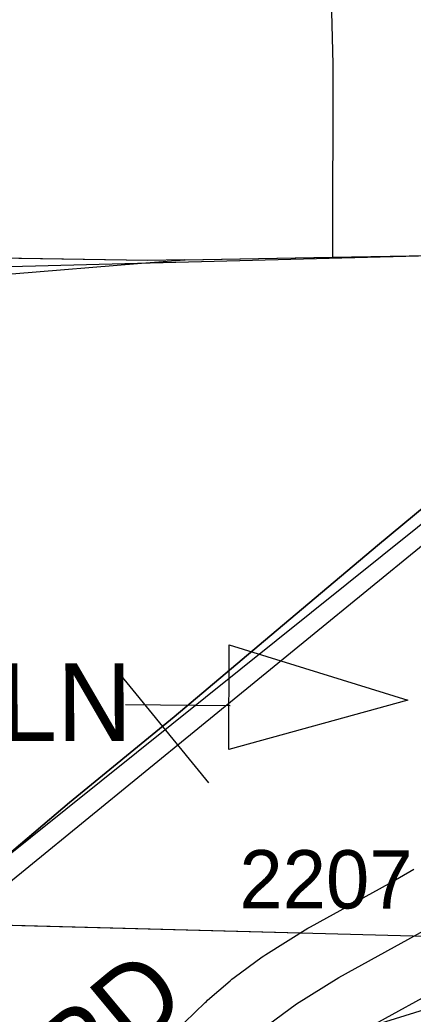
# Model space of a CAD drawing. Extents: x -132.8 to -73.3, y -60 to -26.
# Drawn here: x -118.614 to -118.411, y -48.456 to -47.944 of the extents above; entities that cross this region are included whole.
import ezdxf

# ---------------------------------------------------------------- set-up
doc = ezdxf.new("R2010")
doc.units = 0
for name, color, linetype in [('tdCoCityStreetMajor', 7, 'Continuous'), ('tdCoCorpBndry', 7, 'Continuous'), ('tdCoDirctArrow', 7, 'Continuous'), ('tdCoDivCarto', 7, 'Continuous'), ('tdCoHydroRiver', 7, 'Continuous'), ('tdCoPrimary', 7, 'Continuous'), ('tdCoPriNonDiv', 7, 'Continuous'), ('tdCoPriNonDivCL', 7, 'Continuous'), ('tdCoRRCL', 7, 'Continuous'), ('tdCoSecRdNmbr', 7, 'Continuous'), ('tdCoSecRdTxt', 7, 'Continuous'), ('tdCoSecRteBand', 7, 'Continuous'), ('tdCoSecRteCL', 7, 'Continuous'), ('tdCoSectLine', 7, 'Continuous'), ('tdCoSectLinePart', 7, 'Continuous'), ('tdCoSurfBitum', 7, 'Continuous')]:
    doc.layers.add(name, color=color, linetype=linetype)

msp = doc.modelspace()

# ---------------------------------------------------------------- linework, layer by layer
at = {"layer": 'tdCoCityStreetMajor'}
msp.add_lwpolyline([(-118.45246, -48.06627), (-118.45228, -47.96682), (-118.45549, -47.83809), (-118.45647, -47.76756), (-118.4545, -47.74882), (-118.44858, -47.72909), (-118.43798, -47.70986), (-118.42614, -47.69531), (-118.40765, -47.6815), (-118.38668, -47.67262), (-118.37337, -47.66892), (-118.36119, -47.66821), (-118.36101, -47.6682)], dxfattribs=at)
at = {"layer": 'tdCoCorpBndry'}
msp.add_lwpolyline([(-118.35624, -47.4141), (-118.36119, -47.66821), (-118.3699, -47.97336), (-118.37354, -48.06481), (-118.37608, -48.16042), (-118.37689, -48.19087), (-118.69634, -48.4516), (-118.88124, -48.6063), (-119.00578, -48.72624), (-119.22081, -48.96551)], dxfattribs=at)
at = {"layer": 'tdCoDirctArrow'}
msp.add_line((-118.55933, -48.29678), (-118.50529, -48.2973), dxfattribs=at)
msp.add_lwpolyline([(-118.50583, -48.26602), (-118.41374, -48.29447), (-118.50599, -48.31992)], close=True, dxfattribs=at)
at = {"layer": 'tdCoDivCarto'}
for p, q in [((-118.54791, -48.06798), (-118.63477, -48.06655)), ((-118.55107, -48.06942), (-118.52899, -48.06764)), ((-118.55107, -48.06942), (-118.52899, -48.06764)), ((-118.52899, -48.06764), (-118.54791, -48.06798)), ((-118.61785, -48.07479), (-118.55107, -48.06942)), ((-118.61785, -48.07479), (-118.55107, -48.06942))]:
    msp.add_line(p, q, dxfattribs=at)
for points in [[(-118.52899, -48.06764), (-118.54791, -48.06798), (-118.63477, -48.06655), (-118.67599, -48.06688)], [(-118.52899, -48.06764), (-118.54791, -48.06798), (-118.63477, -48.06655), (-118.67598, -48.06688)], [(-118.52899, -48.06764), (-118.54791, -48.06798), (-118.63477, -48.06655), (-118.67598, -48.06688)], [(-118.55107, -48.06942), (-118.52899, -48.06764)], [(-118.55107, -48.06942), (-118.52899, -48.06764)], [(-118.61785, -48.07479), (-118.55107, -48.06942)], [(-118.61785, -48.07479), (-118.55107, -48.06942)]]:
    msp.add_lwpolyline(points, dxfattribs=at)
at = {"layer": 'tdCoHydroRiver'}
msp.add_lwpolyline([(-117.98585, -48.0942), (-118.01487, -48.11708), (-118.04527, -48.13204), (-118.06628, -48.1504), (-118.0979, -48.21108), (-118.12057, -48.23255), (-118.16562, -48.26447), (-118.21814, -48.2804), (-118.31229, -48.37725), (-118.36757, -48.43729), (-118.38999, -48.4493), (-118.4457, -48.46673), (-118.47166, -48.49285), (-118.50738, -48.52975), (-118.53695, -48.57313), (-118.57957, -48.63193), (-118.60208, -48.64709), (-118.63379, -48.65254), (-118.65762, -48.65821), (-118.69777, -48.68395), (-118.7577, -48.7407), (-118.84316, -48.80781), (-118.87734, -48.84633), (-118.90841, -48.88651)], dxfattribs=at)
at = {"layer": 'tdCoPrimary'}
for p, q in [((-118.55107, -48.06942), (-118.52899, -48.06764)), ((-118.55107, -48.06942), (-118.52899, -48.06764)), ((-118.52899, -48.06764), (-118.52859, -48.06763)), ((-118.52899, -48.06764), (-118.52859, -48.06763)), ((-118.52859, -48.06763), (-118.52857, -48.06763)), ((-118.52859, -48.06763), (-118.52857, -48.06763)), ((-118.61785, -48.07479), (-118.55107, -48.06942)), ((-118.61785, -48.07479), (-118.55107, -48.06942))]:
    msp.add_line(p, q, dxfattribs=at)
for points in [[(-118.52899, -48.06764), (-118.54791, -48.06798), (-118.63477, -48.06655), (-118.67598, -48.06688), (-118.72651, -48.06729), (-118.78287, -48.0686), (-118.78288, -48.0686), (-118.79081, -48.06879), (-118.80074, -48.06902), (-118.82106, -48.07001), (-118.85105, -48.07148), (-118.86386, -48.07176)], [(-118.79917, -48.08377), (-118.74199, -48.08204), (-118.67565, -48.0783), (-118.6283, -48.07563), (-118.61785, -48.07479), (-118.55107, -48.06942), (-118.52899, -48.06764)], [(-118.52899, -48.06764), (-118.54791, -48.06798), (-118.63477, -48.06655), (-118.67598, -48.06688)], [(-118.52899, -48.06764), (-118.54791, -48.06798), (-118.63477, -48.06655), (-118.67598, -48.06688)], [(-118.52899, -48.06764), (-118.52859, -48.06763), (-118.52857, -48.06763), (-118.45246, -48.06627), (-118.45197, -48.06626), (-118.38293, -48.06502)], [(-118.52857, -48.06763), (-118.45246, -48.06627), (-118.45197, -48.06626)], [(-118.52857, -48.06763), (-118.45246, -48.06627), (-118.45197, -48.06626)], [(-118.45197, -48.06626), (-118.38293, -48.06502), (-118.37354, -48.06476)], [(-118.45197, -48.06626), (-118.38293, -48.06502), (-118.37354, -48.06476)]]:
    msp.add_lwpolyline(points, dxfattribs=at)
at = {"layer": 'tdCoPriNonDiv'}
msp.add_lwpolyline([(-118.61889, -48.0711), (-118.3293, -48.06354), (-117.75619, -48.05368), (-117.65212, -48.05121), (-117.45927, -48.03864), (-117.03141, -48.00732), (-116.85509, -47.99375), (-116.65238, -47.97994), (-116.54954, -47.97797), (-115.84942, -47.98956), (-115.38137, -47.99449), (-115.06398, -47.99893)], dxfattribs=at)
at = {"layer": 'tdCoPriNonDivCL'}
for points in [[(-118.52937, -48.06764), (-118.52897, -48.06763), (-118.45284, -48.06627), (-118.38331, -48.06502), (-118.37392, -48.06476), (-118.37392, -48.06476), (-118.37353, -48.06475), (-118.3293, -48.06354), (-118.29791, -48.06338), (-118.2314, -48.06305), (-118.21913, -48.06281), (-118.1298, -48.06108), (-118.09528, -48.06035), (-118.0245, -48.05886), (-117.92277, -48.05679), (-117.89083, -48.05614), (-117.89044, -48.05614), (-117.86458, -48.05566), (-117.86419, -48.05566), (-117.75619, -48.05368), (-117.65212, -48.05121), (-117.56975, -48.04677), (-117.45927, -48.03864), (-117.42909, -48.03615)], [(-118.52897, -48.06763), (-118.45284, -48.06627), (-118.38331, -48.06502), (-118.37392, -48.06476), (-118.37353, -48.06475), (-118.37353, -48.06475), (-118.3293, -48.06354), (-118.29791, -48.06338), (-118.2314, -48.06305), (-118.21913, -48.06281), (-118.1298, -48.06108), (-118.09528, -48.06035), (-118.0245, -48.05886), (-117.92277, -48.05679), (-117.89083, -48.05614), (-117.89044, -48.05614), (-117.86458, -48.05566), (-117.86419, -48.05566), (-117.75619, -48.05368), (-117.65212, -48.05121), (-117.56975, -48.04677), (-117.45927, -48.03864), (-117.42909, -48.03615)]]:
    msp.add_lwpolyline(points, dxfattribs=at)
at = {"layer": 'tdCoRRCL'}
msp.add_line((-118.56397, -48.27909), (-118.51652, -48.33717), dxfattribs=at)
for points in [[(-119.04345, -48.75425), (-119.0096, -48.71656), (-118.97392, -48.67777), (-118.94977, -48.65307), (-118.93586, -48.64062), (-118.91079, -48.61702), (-118.88261, -48.59396), (-118.87411, -48.58703), (-118.85279, -48.56963), (-118.82132, -48.5431), (-118.78637, -48.51345), (-118.75343, -48.48619), (-118.71683, -48.45527), (-118.68902, -48.43185), (-118.64913, -48.39909), (-118.5882, -48.34731), (-118.53422, -48.30321), (-118.49049, -48.26625), (-118.42937, -48.21483), (-118.38418, -48.17732)], [(-118.38418, -48.17732), (-118.42937, -48.21483), (-118.49049, -48.26625), (-118.53422, -48.30321), (-118.5882, -48.34731), (-118.64913, -48.39909), (-118.68902, -48.43185), (-118.71683, -48.45527), (-118.75343, -48.48619), (-118.78637, -48.51345), (-118.82132, -48.5431), (-118.85279, -48.56963), (-118.87411, -48.58703), (-118.88261, -48.59396), (-118.91079, -48.61702), (-118.93586, -48.64062), (-118.94977, -48.65307), (-118.97392, -48.67777), (-119.0096, -48.71656), (-119.04345, -48.75425)], [(-120.90014, -50.91758), (-120.80482, -50.8333), (-120.69913, -50.71459), (-120.38749, -50.3671), (-120.27515, -50.19914), (-119.95857, -49.75638), (-119.76019, -49.4486), (-119.624, -49.31017), (-119.6013, -49.2871), (-119.53026, -49.22585), (-119.46076, -49.16298), (-119.40286, -49.1219), (-119.33353, -49.06534), (-119.1714, -48.90077), (-118.98751, -48.68786), (-118.88892, -48.59894), (-118.66302, -48.40922), (-118.39059, -48.19074)]]:
    msp.add_lwpolyline(points, dxfattribs=at)
at = {"layer": 'tdCoSecRteBand'}
for points in [[(-118.52885, -48.46074), (-118.51825, -48.45039), (-118.51764, -48.4498), (-118.51701, -48.44924), (-118.50542, -48.43913), (-118.50443, -48.43827), (-118.50336, -48.43749), (-118.48881, -48.42689), (-118.48795, -48.42626), (-118.48704, -48.42569), (-118.46534, -48.41213), (-118.46465, -48.4117), (-118.46393, -48.4113), (-118.42344, -48.38897), (-118.41071, -48.38169)], [(-118.39427, -48.4414), (-118.43424, -48.46344)]]:
    msp.add_lwpolyline(points, dxfattribs=at)
at = {"layer": 'tdCoSecRteCL'}
msp.add_lwpolyline([(-118.95499, -48.91056), (-118.90887, -48.8499), (-118.87089, -48.80255), (-118.8598, -48.788), (-118.84993, -48.7769), (-118.83859, -48.7658), (-118.81861, -48.75002), (-118.77891, -48.72166), (-118.65807, -48.63584), (-118.60678, -48.60008), (-118.59346, -48.59047), (-118.58113, -48.57937), (-118.56905, -48.56605), (-118.55573, -48.54756), (-118.53107, -48.51427), (-118.51948, -48.49725), (-118.50789, -48.48221), (-118.49729, -48.47185), (-118.48569, -48.46174), (-118.47114, -48.45113), (-118.44944, -48.43757), (-118.40875, -48.41513), (-118.38976, -48.40428), (-118.38121, -48.39765)], dxfattribs=at)
at = {"layer": 'tdCoSectLine'}
msp.add_lwpolyline([(-118.88204, -48.40349), (-117.88235, -48.43017)], dxfattribs=at)
at = {"layer": 'tdCoSectLinePart'}
msp.add_lwpolyline([(-118.64551, -48.4098), (-118.46943, -48.4145)], dxfattribs=at)
at = {"layer": 'tdCoSurfBitum'}
msp.add_lwpolyline([(-118.95499, -48.91056), (-118.90887, -48.8499), (-118.87089, -48.80255), (-118.8598, -48.788), (-118.84993, -48.7769), (-118.83859, -48.7658), (-118.81861, -48.75002), (-118.77891, -48.72166), (-118.65807, -48.63584), (-118.60678, -48.60008), (-118.59346, -48.59047), (-118.58113, -48.57937), (-118.56905, -48.56605), (-118.55573, -48.54756), (-118.53107, -48.51427), (-118.51948, -48.49725), (-118.50789, -48.48221), (-118.49729, -48.47185), (-118.48569, -48.46174), (-118.47114, -48.45113), (-118.44944, -48.43757), (-118.40875, -48.41513)], dxfattribs=at)

# ---------------------------------------------------------------- texts
at = {"layer": 'tdCoSecRdNmbr'}
msp.add_text('2207', height=0.03, rotation=359.9115, dxfattribs=at).set_placement((-118.50063, -48.40181))
at = {"layer": 'tdCoSecRdTxt'}
for s, rotation, p in [('EMBASSY LN', 0.0699, (-118.89781, -48.31594)), ('SUNNYDALE RD', 39.7596, (-118.84791, -48.71944))]:
    msp.add_text(s, height=0.04, rotation=rotation, dxfattribs=at).set_placement(p)

doc.saveas('drawing.dxf')
